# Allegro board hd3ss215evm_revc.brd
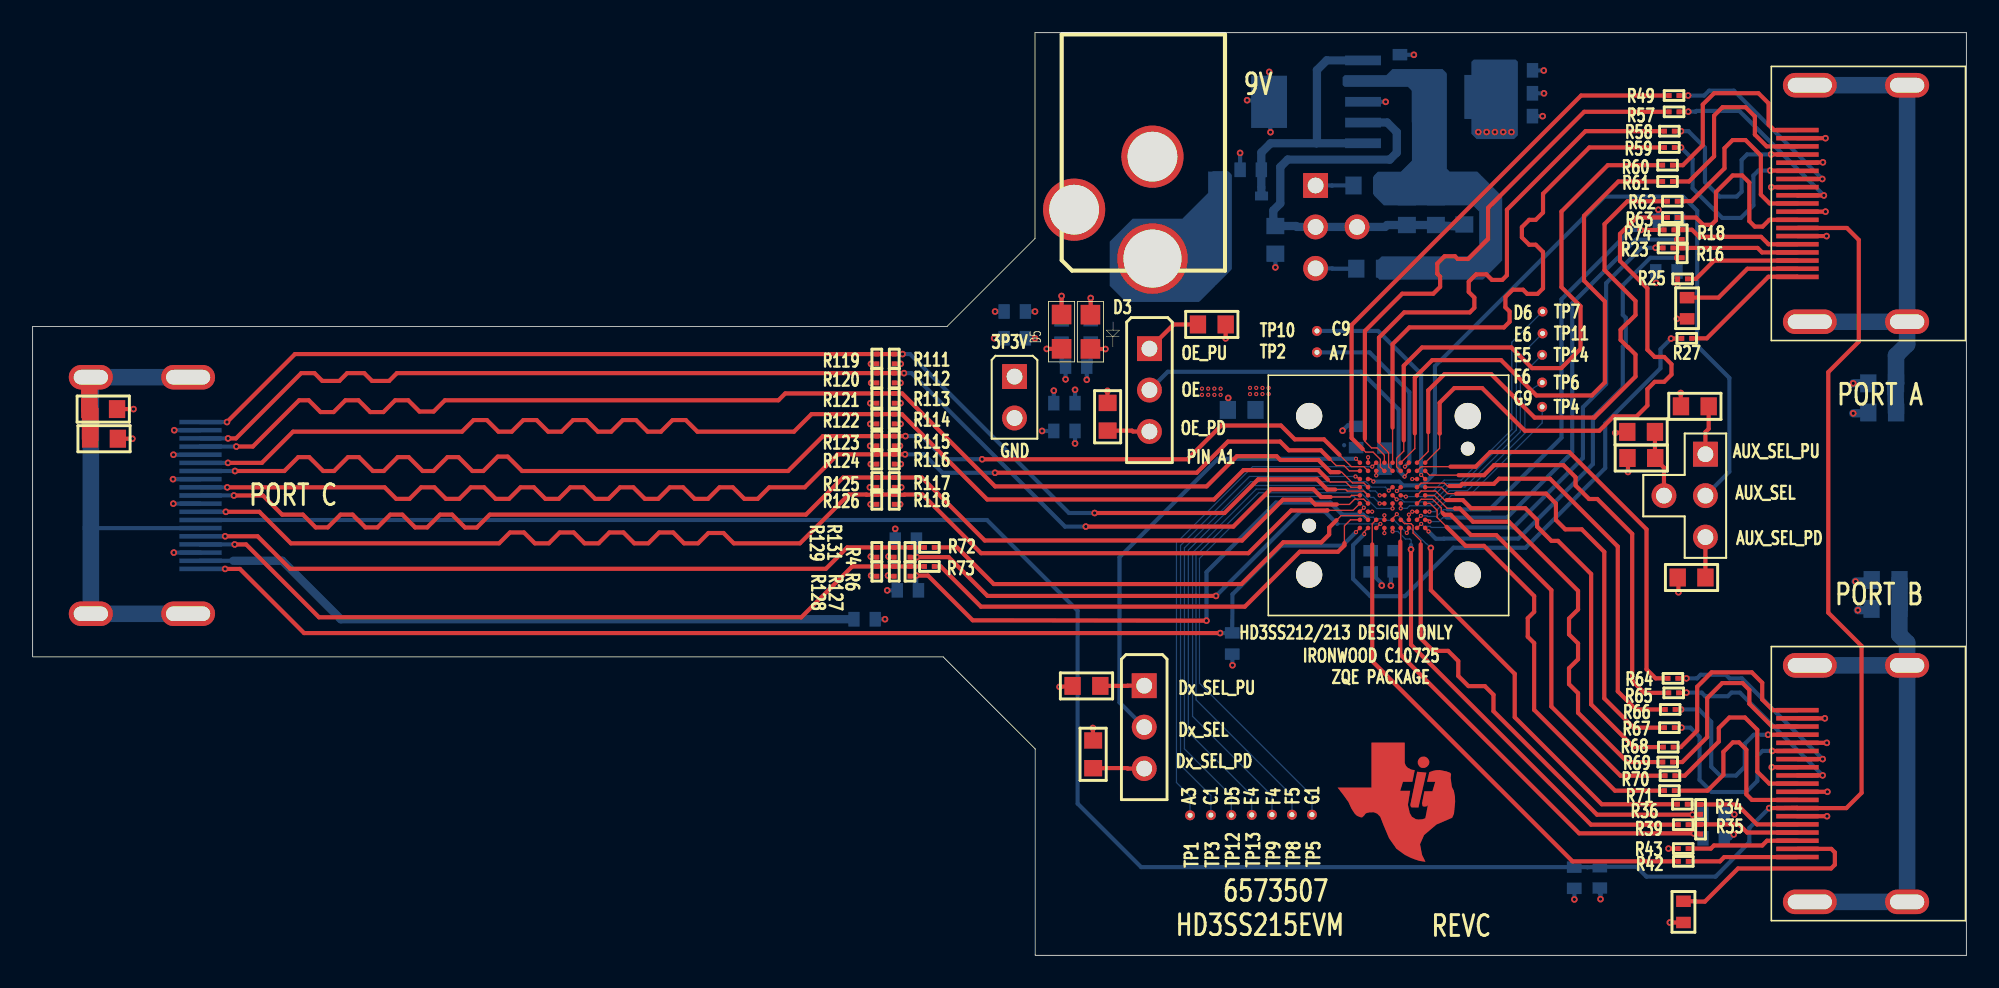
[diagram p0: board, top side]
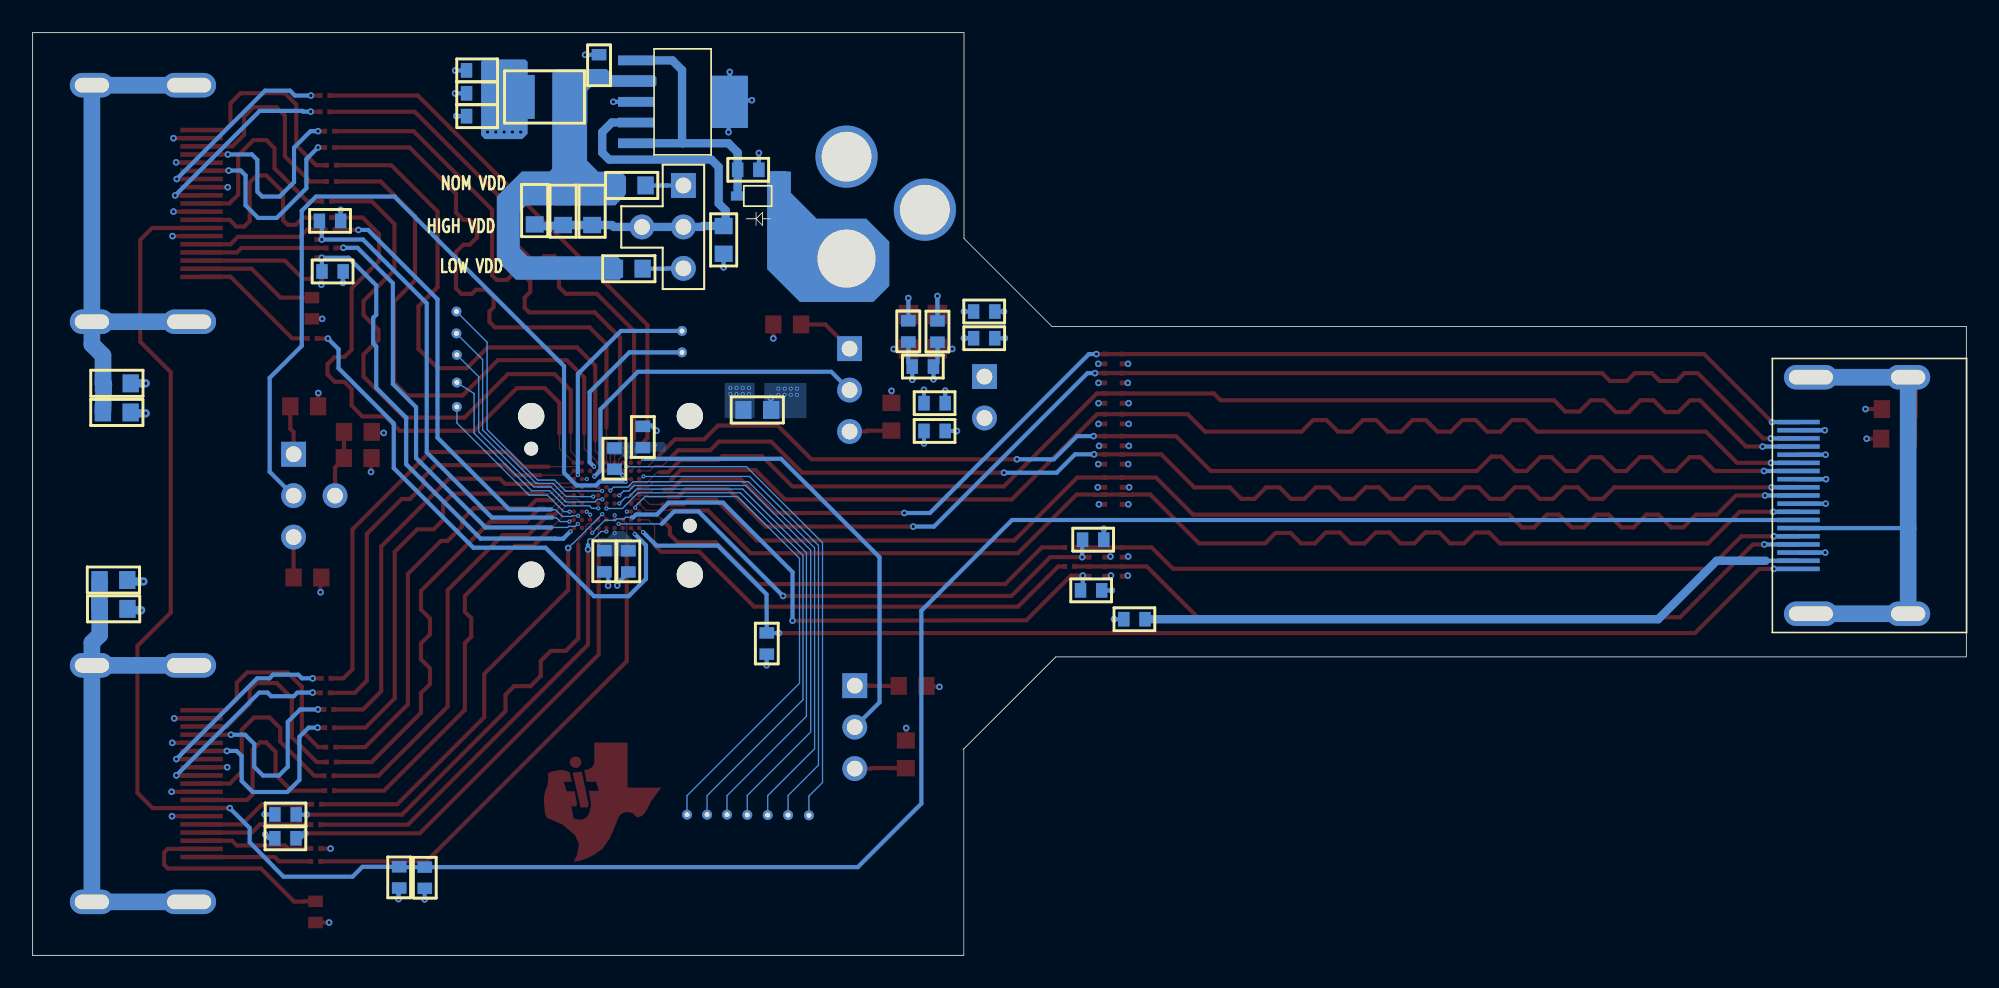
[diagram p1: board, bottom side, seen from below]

Outline 118.49 x 56.56 mm; copper layers: TOP, L2, L3, L4, L5, BOTTOM. Coordinates in mm from the lower left corner of the outline.
Outline path: 0,38.55 0,18.32 0.02,18.3 55.79,18.3 61.43,12.66 61.43,0.02 61.45,0 118.49,0 118.49,56.55 118.49,56.56 61.42,56.56 61.42,43.94 56.03,38.55 0,38.55

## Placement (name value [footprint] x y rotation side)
C20  1.0uF  [0603]  114.18 35.06 180 bottom
C37  1.0uF  [0603]  114.38 21.24 180 bottom
C65  0.1uF  [0402]  90.61 54.25 0 bottom
C66  0.01uF  [0402]  90.6 52.84 0 bottom
C67  1.0uF  [0402]  75.29 48.15 180 bottom
C68  0.1uF  [0402]  83.46 24.81 270 bottom
C69  0.1uF  [0402]  81.1 31.13 90 bottom
C70  0.01uF  [0402]  81.99 24.8 270 bottom
C71  0.01uF  [0402]  82.84 31.1 270 bottom
C73  1.0 uF  [0402]  90.6 51.44 0 bottom
C74  1.0 uF  [0402]  83.78 53.91 90 bottom
C75  1.0uF  [0603]  3.47 33.48 0 top
C76  0.1uF  [0402]  62.58 32.14 0 bottom
C77  0.1uF  [0402]  62.58 33.85 0 bottom
C78  0.01uF  [0402]  60.83 37.83 180 bottom
C79  0.01uF  [0402]  60.83 39.47 180 bottom
D3  GREEN  [LED_HSMB_C170DRA]  64.82 37.17 90 top
D4  10V, 3A  [SOD323]  74.06 46.55 180 bottom
D5  GREEN  [LED_HSMB_C170DRA]  63.05 37.18 90 top
J18  HDMI Female  [MOLEX_HDMI]  10.29 28.19 90 bottom
J21  HDMI Female  [MOLEX_HDMI]  108.14 46.09 90 top
J22  HDMI Female  [MOLEX_HDMI]  108.14 10.53 90 top
JMP4  4 Pin-T Berg Jumper  [BERG2X3TEE]  102.5 30.72 270 top
JMP9  DNI  [BERG2]  60.17 35.48 0 top
JMP10  DNI  [BERG2X3TEE]  78.62 47.19 270 bottom
JMP11  Header 3x1  [BERG1X3]  68.44 37.19 0 top
JMP13  Header 3x1  [BERG1X3]  68.12 16.53 0 top
L2  HI1206N101R-00  [1210]  85.73 52.62 0 bottom
NOREF  -  []  83.65 10.08 0 top
P1  RAPC722  [CON_RAPC722_JACK_THVT_3]  68.62 45.83 180 top
R2  DNI 100k  [0402]  73.51 18.46 90 bottom
R4  0  [0201]  53.76 25.01 270 top
R5  0  [0402]  51.63 20.6 180 bottom
R6  0  [0201]  53.76 23.84 270 top
R7  2K  [0402]  52.86 25.48 0 bottom
R8  2K  [0402]  52.98 22.37 0 bottom
R9  DNI 27K  [0402]  94.47 4.11 90 bottom
R10  DNI 5M  [0402]  96.03 5.43 270 bottom
R11  1M  [0603]  114.19 33.28 180 bottom
R14  100K  [0402]  100.76 41.92 180 bottom
R16  DNI 0  [0201]  101.08 42.76 90 top
R17  100K  [0402]  99.62 45.02 0 bottom
R18  DNI 0  [0201]  101.08 43.88 90 top
R20  0  [0402]  101.38 40.32 270 top
R22  4.64K  [0603]  73.11 38.67 180 top
R23  0  [0201]  99.91 43.36 0 top
R24  4.64K  [0603]  65.87 32.16 90 top
R25  0  [0201]  100.8 41.47 0 top
R27  0  [0201]  101.06 37.82 0 top
R28  4.64K  [0603]  101.01 33.66 0 top
R29  4.64K  [0603]  63.73 16.52 0 top
R30  4.64K  [0603]  102.5 23.16 180 top
R31  4.64K  [0603]  64.99 11.47 90 top
R33  100K  [0402]  103.65 8.64 180 bottom
R34  DNI 0  [0201]  102.21 8.65 90 top
R35  DNI 0  [0201]  102.21 7.43 90 top
R36  0  [0201]  100.79 9.26 0 top
R39  0  [0201]  100.84 8.01 0 top
R42  0  [0201]  100.85 5.76 0 top
R43  0  [0201]  100.84 6.55 0 top
R44  0  [0402]  101.16 3.31 270 top
R45  100K  [0402]  102.35 7.18 0 bottom
R46  1M  [0603]  114.39 23.01 180 bottom
R47  4.64K  [0603]  99.43 30.49 180 top
R48  4.64K  [0603]  97.71 32.09 0 top
R49  0  [0201]  100.28 52.7 0 top
R50  75  [0402]  64.84 37.6 90 bottom
R51  23.2K  [0603]  84.21 46.47 270 bottom
R52  150K  [0603]  85.99 46.47 270 bottom
R53  150K  [0603]  82.64 47.19 180 bottom
R54  DNI  [0603]  87.73 46.5 270 bottom
R55  64.9K  [0603]  82.81 42.09 180 bottom
R56  13K  [0603]  76.15 44.71 270 bottom
R57  0  [0201]  100.28 51.71 0 top
R58  0  [0201]  100 50.52 0 top
R59  0  [0201]  100 49.52 0 top
R60  0  [0201]  99.88 48.44 0 top
R61  0  [0201]  99.88 47.44 0 top
R62  0  [0201]  100.18 46.23 0 top
R63  0  [0201]  100.18 45.22 0 top
R64  0  [0201]  100.21 16.98 0 top
R65  0  [0201]  100.26 16.09 0 top
R66  0  [0201]  100.05 15.07 0 top
R67  0  [0201]  100 13.96 0 top
R68  0  [0201]  99.93 12.76 0 top
R69  0  [0201]  99.89 11.85 0 top
R70  0  [0201]  100.03 11.01 0 top
R71  0  [0201]  100 10.1 0 top
R72  DNI 0  [0201]  54.65 25.01 0 top
R73  DNI 0  [0201]  54.65 23.84 0 top
R74  0  [0201]  99.97 44.47 0 top
R75  0  [0603]  73.24 33.43 0 bottom
R111  DNI 10K  [0201]  52.8 36.26 90 top
R112  DNI 10K  [0201]  52.8 35.09 90 top
R113  DNI 10K  [0201]  52.8 33.85 90 top
R114  DNI 10K  [0201]  52.8 32.58 90 top
R115  DNI 10K  [0201]  52.8 31.23 90 top
R116  DNI 10K  [0201]  52.8 30.11 90 top
R117  DNI 10K  [0201]  52.8 28.69 90 top
R118  DNI 10K  [0201]  52.8 27.65 90 top
R119  DNI 10K  [0201]  51.73 36.26 90 top
R120  DNI 10K  [0201]  51.73 35.09 90 top
R121  DNI 10K  [0201]  51.73 33.85 90 top
R122  DNI 10K  [0201]  51.73 32.58 90 top
R123  DNI 10K  [0201]  51.73 31.23 90 top
R124  DNI 10K  [0201]  51.73 30.11 90 top
R125  DNI 10K  [0201]  51.73 28.69 90 top
R126  DNI 10K  [0201]  51.73 27.65 90 top
R127  DNI 1M  [0201]  52.8 23.84 270 top
R128  DNI 1M  [0201]  51.73 23.84 270 top
R129  DNI 10K  [0201]  51.73 25.01 270 top
R131  DNI 10K  [0201]  52.8 25.01 270 top
R132  100  [0402]  63.05 37.59 90 bottom
R133  DNI 0  [0402]  64.59 36.09 180 bottom
R134  1M  [0603]  3.52 31.67 0 top
TP1  Test Point  [TESTPOINTDRA]  70.92 8.59 0 top
TP2  Test Point  [TESTPOINTDRA]  78.7 36.96 0 top
TP3  Test Point  [TESTPOINTDRA]  72.2 8.6 0 top
TP4  Test Point  [TESTPOINTDRA]  92.5 33.62 0 top
TP5  Test Point  [TESTPOINTDRA]  78.39 8.62 0 top
TP6  Test Point  [TESTPOINTDRA]  92.5 35.11 0 top
TP7  Test Point  [TESTPOINTDRA]  92.52 39.46 0 top
TP8  Test Point  [TESTPOINTDRA]  77.17 8.62 0 top
TP9  Test Point  [TESTPOINTDRA]  75.94 8.62 0 top
TP10  Test Point  [TESTPOINTDRA]  78.7 38.28 0 top
TP11  Test Point  [TESTPOINTDRA]  92.52 38.12 0 top
TP12  Test Point  [TESTPOINTDRA]  73.45 8.6 0 top
TP13  Test Point  [TESTPOINTDRA]  74.7 8.61 0 top
TP14  Test Point  [TESTPOINTDRA]  92.5 36.81 0 top
U4  REG104-A  [DCQ_R-PDSO-G6]  78.67 52.32 180 bottom
U5  HD3SS215_ZQE  [IRONWOOD_81PIN_7048]  78.22 33.06 180 top

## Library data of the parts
C20 C37 C75 = cc0603
C65-C71 C73 C74 C76-C79 = cc0402
D3 D5 = LED_0603
D4 = BAT60A
J18 = HDMI A plug connector
J21 J22 = HDMI A plug connector1
JMP4 JMP10 = 4 Pin-T Berg Jumper
JMP9 = 2 Pin Berg Jumper
JMP11 JMP13 = Header 3x1
L2 = Ferrite Bead_1210_HI1206N10R-00
P1 = RAPC722
R2 R4-R10 R14 R16-R18 R20 R23 R25 R27 R33-R36 R39 R42-R45 R49-R75 R132 = r0402
R11 R22 R24 R28-R31 R46-R48 R134 = r0603
R111-R129 R131 = r0201
R133 = R
TP1-TP14 = Test Point
U4 = REG104
U5 = HD3SS213 ZQE_1

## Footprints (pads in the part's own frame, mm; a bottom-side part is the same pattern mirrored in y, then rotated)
0201
  rect 0.3x0.3 smd: 1(0,0) 2(0.599,0)
0402
  rect 0.701x0.899 smd: 1(0,0) 2(1.3,0)
0603
  rect 1.001x1.1 smd: 1(0,0) 2(1.699,0)
1210
  rect 1.6x2.7 smd: 1(0,0) 2(2.799,0)
BERG1X3
  rect 1.524x1.524 hole 0.965: 1(0,0)
  round 1.524 hole 0.965: 2(0,-2.54) 3(0,-5.08)
BERG2
  rect 1.524x1.524 hole 0.965: 1(0,0)
  round 1.524 hole 0.965: 2(0,-2.54)
BERG2X3TEE
  rect 1.524x1.524 hole 0.965: 1(0,0)
  round 1.524 hole 0.965: 2(2.54,0) 3(5.08,0) 4(2.54,-2.54)
CON_RAPC722_JACK_THVT_3
  round 3.81 hole 3.048: 1(0,-3.124) 2(4.801,0.127)
  round 4.318 hole 3.556: 3(0,3.124)
DCQ_R-PDSO-G6
  rect 2.2x0.599 smd: 1(-2.857,2.54) 2(-2.857,1.27) 3(-2.857,0) 4(-2.857,-1.27) 5(-2.857,-2.54)
  rect 2.2x3.2 smd: 6(2.901,0)
IRONWOOD_81PIN_7048
  round 1.61 hole 1.61 unplated: (-9.721,9.721) (-9.721,0) (0,9.721) (0,0)
  round 0.851 hole 0.851 unplated: (-9.721,1.999) (0,6.721)
  round 0.279 smd: A1(-3.109,2.86) A2(-3.609,2.86) A3(-4.11,2.86) A4(-4.61,2.86) A5(-5.11,2.86) A6(-5.611,2.86) A7(-6.111,2.86) A8(-6.609,2.86) A9(-7.109,2.86) B1(-3.109,3.36) B2(-3.609,3.36) B3(-4.11,3.36) B4(-4.61,3.36) B5(-5.11,3.36) B6(-5.611,3.36) B7(-6.111,3.36) B8(-6.609,3.36) B9(-7.109,3.36) C1(-3.109,3.861) C2(-3.609,3.861) C8(-6.609,3.861) C9(-7.109,3.861) D1(-3.109,4.361) D2(-3.609,4.361) D5(-5.11,4.361) D6(-5.611,4.361) D8(-6.609,4.361) D9(-7.109,4.361) E1(-3.109,4.859) E2(-3.609,4.859) E4(-4.61,4.859) E5(-5.11,4.859) E6(-5.611,4.859) E8(-6.609,4.859) E9(-7.109,4.859) F1(-3.109,5.359) F2(-3.609,5.359) F4(-4.61,5.359) F5(-5.11,5.359) F6(-5.611,5.359) F8(-6.609,5.359) F9(-7.109,5.359) G1(-3.109,5.86) G2(-3.609,5.86) G8(-6.609,5.86) G9(-7.109,5.86) H1(-3.109,6.36) H2(-3.609,6.36) H3(-4.11,6.36) H4(-4.61,6.36) H5(-5.11,6.36) H6(-5.611,6.36) H7(-6.111,6.36) H8(-6.609,6.36) H9(-7.109,6.36) J1(-3.109,6.861) J2(-3.609,6.861) J3(-4.11,6.861) J4(-4.61,6.861) J5(-5.11,6.861) J6(-5.611,6.861) J7(-6.111,6.861) J8(-6.609,6.861) J9(-7.109,6.861)
LED_HSMB_C170DRA
  rect 1.199x1.199 smd: 1(0,0) 2(2.101,0)
MOLEX_HDMI
  rect 0.279x2.601 smd: 1(4.501,0) 2(4,0) 3(3.5,0) 4(3,0) 5(2.499,0) 6(1.999,0) 7(1.501,0) 8(1.001,0) 9(0.5,0) 10(0,0) 11(-0.5,0) 12(-1.001,0) 13(-1.501,0) 14(-1.999,0) 15(-2.499,0) 16(-3,0) 17(-3.5,0) 18(-4,0) 19(-4.501,0)
  oval 1.501x3.299 hole 0.899x2.7: 20(-7.249,-0.759) 21(7.249,-0.759)
  oval 1.501x2.7 hole 0.899x2.101: 22(-7.249,-6.721) 23(7.249,-6.721)
SOD323
  rect 0.8x0.551 smd: 1(-1.24,0) 2(1.24,0)
TESTPOINTDRA
  round 0.61 hole 0.305: 1(0,0)

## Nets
9V_DC_IN: C67.1 D4.1(C) U4.1(VIN) U4.5(ENABLE)
9V_WALL_IN: D4.2(A) P1.3(TIP)
GND: C20.2 C37.2 C65.2 C66.2 C67.2 C68.2 C69.2 C70.2 C71.2 C73.2 C74.2 C75.2 C76.2 C77.2 C78.2 C79.2 D3.1 D5.1 J18.2(GND1) J18.5(GND2) J18.8(GND3) J18.11(GND4) J18.17(DDC GND) J21.2(GND1) J21.5(GND2) J21.8(GND3) J21.11(GND4) J21.14(UTILITY) J22.2(GND1) J22.5(GND2) J22.8(GND3) J22.11(GND4) J22.14(UTILITY) JMP9.2 P1.1(SLEEVE) R2.1 R10.2 R11.2 R17.1 R24.2 R25.1 R30.2 R31.2 R33.1 R43.1 R46.2 R47.2 R56.2 R119.1 R120.1 R121.1 R122.1 R123.1 R124.1 R125.1 R126.1 R128.2 R129.2 R134.2 U4.3(GND1) U4.6(GND2) U5.B3(GND#B3) U5.C8(GND#C8) U5.G2(GND#G2) U5.G8(GND#G8) U5.H4(GND#H4) U5.H7(GND#H7)
SGND2: C20.1 J21.20(CH_GND1) J21.21(CH_GND2) J21.22(CH_GND3) J21.23(CH_GND4) R11.1
SGND3: C37.1 J22.20(CH_GND1) J22.21(CH_GND2) J22.22(CH_GND3) J22.23(CH_GND4) R46.1
3P3V: C65.1 C66.1 C73.1 JMP9.1 L2.2 R14.2 R22.1 R28.1 R29.1 R45.2 R48.1 R50.1 R75.1 R111.1 R112.1 R113.1 R114.1 R115.1 R116.1 R117.1 R118.1 R127.2 R131.2 R133.1
3P3V_R: C68.1 C69.1 C70.1 C71.1 R75.2 U5.A2(VCC#A2) U5.J4(VCC#J4)
3P3V_REG: C74.1 L2.1 R51.1 R52.1 R53.1 R54.1 R55.1 U4.2(VOUT)
5V/3P3V: C76.1 C77.1 C78.1 C79.1 R5.1 R7.1 R8.1 R9.1 R20.2 R44.2 R132.1 R133.2
AUX SEL: JMP4.2 U5.C2(AUX_SEL)
AUX SEL MID: JMP4.4 R47.1 R48.2
AUX SEL PULL DOWN: JMP4.3 R30.1
AUX SEL PULL UP: JMP4.1 R28.2
AUX_SINK_OUTPUT_N: R14.1 R16.1 U5.J9(DA_AUX_N)
AUX_SINK_OUTPUT_N_DDC_SDA: J21.16(SDA) R16.2 R23.2
AUX_SINK_OUTPUT_P: R17.2 R18.1 U5.H9(DA_AUX_P)
AUX_SINK_OUTPUT_P_DDC_SCL: J21.15(SCL) R18.2 R74.2
CEC: J18.13(CEC) J21.13(CEC) J22.13(CEC) R9.2 R10.1
DA_0N: R57.1 U5.A4(DA_0_N)
DA_0P: R49.1 U5.B4(DA_0_P)
DA_1N: R59.1 U5.A5(DA_1_N)
DA_1P: R58.1 U5.B5(DA_1_P)
DA_2N: R61.1 U5.A6(DA_2_N)
DA_2P: R60.1 U5.B6(DA_2_P)
DA_CLKN: R63.1 U5.A9(DA_3_N)
DA_CLKP: R62.1 U5.A8(DA_3_P)
DA_HPD: R27.1 U5.J2(DA_HPD)
DA_HPD_R: J21.19(HPD) R27.2
DB_0N: R65.1 U5.B9(DB_0_N)
DB_0P: R64.1 U5.B8(DB_0_P)
DB_1N: R67.1 U5.D9(DB_1_N)
DB_1P: R66.1 U5.D8(DB_1_P)
DB_2N: R69.1 U5.E9(DB_2_N)
DB_2P: R68.1 U5.E8(DB_2_P)
DB_AUX_SINK_OUTPUT_N: R35.1 R45.1 U5.J6(DB_AUX_N)
DB_AUX_SINK_OUTPUT_N_OR_SDA: J22.16(SDA) R35.2 R39.2
DB_AUX_SINK_OUTPUT_P: R33.2 R34.1 U5.H6(DB_AUX_P)
DB_AUX_SINK_OUTPUT_P_OR_DDC_SCL: J22.15(SCL) R34.2 R36.2
DB_CLKN: R71.1 U5.F9(DB_3_N)
DB_CLKP: R70.1 U5.F8(DB_3_P)
DB_DDC_SCL: R36.1 U5.H5(DB_DDCCLK)
DB_DDC_SDA: R39.1 U5.J5(DB_DDCDBT)
DB_HPD: R42.1 U5.H3(DB_HPD)
DB_HPD_R: J22.19(HPD) R42.2
DDC_SCL: R74.1 U5.H8(DA_DDCCLK)
DDC_SDA: R23.1 U5.J8(DA_DDCDAT)
DX SEL PULL DOWN: JMP13.3 R31.1
DX SEL PULL UP: JMP13.1 R29.2
DX_SEL: JMP13.2 U5.A1(DX_SEL)
HIGH VDD: JMP10.2 JMP10.4 R51.2 R52.2 R54.2 R56.1 U4.4(NR/ADJUST)
LOW VDD: JMP10.3 R55.2
NOM VDD: JMP10.1 R53.2
OE PULL DOWN: JMP11.3 R24.1
OE PULL UP: JMP11.1 R22.2
OUTPUT ENABLE: JMP11.2 U5.B7(OE)
SOURCE_CLK_N: J18.12(CLKN) R118.2 R126.2 U5.F1(DC_3_N)
SOURCE_CLK_P: J18.10(CLKP) R117.2 R125.2 U5.F2(DC_3_P)
SOURCE_DDC_CLK: R4.2 R7.2 U5.J3(DC_DDC_CLK)
SOURCE_DDC_SDA: R6.2 R8.2 U5.J7(DC_DDC_SDA)
SOURCE_DP_AUX_N_C: R73.2 U5.H1(DC_AUX_N)
SOURCE_DP_AUX_P_C: R72.2 U5.H2(DC_AUX_P)
SOURCE_HPD_C: J18.19(HPD) R2.2 U5.J1(DC_HPD)
SOURCE_TMDS_CLK_P: J18.15(SCL) R4.1 R72.1 R129.1 R131.1
SOURCE_TMDS_ML_0N: J18.3(D2N) R112.2 R120.2 U5.E1(DC_0_N)
SOURCE_TMDS_ML_0P: J18.1(D2P) R111.2 R119.2 U5.E2(DC_0_P)
SOURCE_TMDS_ML_1N: J18.6(D1N) R114.2 R122.2 U5.D1(DC_1_N)
SOURCE_TMDS_ML_1P: J18.4(D1P) R113.2 R121.2 U5.D2(DC_1_P)
SOURCE_TMDS_ML_2N: J18.9(D0N) R116.2 R124.2 U5.B1(DC_2_N)
SOURCE_TMDS_ML_2P: J18.7(D0P) R115.2 R123.2 U5.B2(DC_2_P)
SOURCE_TMDS_SDA_N: J18.16(SDA) R6.1 R73.1 R127.1 R128.1
N16816313: D3.2 R50.2
N16845167: J18.18(5V) R5.2
N17461751: J21.7(D0P) R49.2
N17461760: J21.9(D0N) R57.2
N17461769: J21.4(D1P) R58.2
N17461772: J21.6(D1N) R59.2
N17461775: J21.1(D2P) R60.2
N17461784: J21.3(D2N) R61.2
N17461793: J21.10(CLKP) R62.2
N17461802: J21.12(CLKN) R63.2
N17518625: J21.18(5V) R20.1
N17521117: J22.7(D0P) R64.2
N17521123: J22.9(D0N) R65.2
N17521129: J22.4(D1P) R66.2
N17521131: J22.6(D1N) R67.2
N17521133: J22.1(D2P) R68.2
N17521137: J22.3(D2N) R69.2
N17521143: J22.10(CLKP) R70.2
N17521149: J22.12(CLKN) R71.2
N17522573: J22.17(DDC GND) R43.2
N17522869: J22.18(5V) R44.1
N17527182: TP1.1 U5.A3(NC1)
N17527888: TP2.1 U5.A7(NC2)
N17528001: TP3.1 U5.C1(NC3)
N17528028: TP4.1 U5.G9(NC14)
N17528033: TP5.1 U5.G1(NC13)
N17528049: TP6.1 U5.F6(NC12)
N17528125: TP8.1 U5.F5(NC11)
N17528132: TP7.1 U5.D6(NC4)
N17528155: TP10.1 U5.C9(NC5)
N17528163: TP9.1 U5.F4(NC10)
N17528201: TP12.1 U5.D5(NC6)
N17528206: TP11.1 U5.E6(NC9)
N17528242: TP13.1 U5.E4(NC7)
N17528247: TP14.1 U5.E5(NC8)
N17577047: D5.2 R132.2
N17584630: J21.17(DDC GND) R25.2
N17593880: C75.1 J18.14(UTILITY) J18.20(CH_GND1) J18.21(CH_GND2) J18.22(CH_GND3) J18.23(CH_GND4) R134.1

Pads without a net: P1 2

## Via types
v1: diameter 0.406, hole 0.203, TOP to BOTTOM, 146 vias
v2: diameter 0.254, hole 0.127, TOP to BOTTOM, 51 vias

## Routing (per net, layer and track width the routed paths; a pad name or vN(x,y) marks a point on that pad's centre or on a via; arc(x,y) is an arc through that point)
9V_DC_IN: length 16.7
  BOTTOM w0.508: D4.1 75.29,47.09 C67.1 75.29,49.21 75.86,49.78 78.66,49.78 ; 78.66,49.78 U4.5 ; 78.66,49.78 78.7,49.82 78.7,54.26 79.29,54.86 U4.1
GND: length 88.7
  TOP w0.076: U5.G8 v2(84.54,27.2) ; U5.H4 v2(82.83,26.97) ; U5.C8 v2(84.54,29.2) ; U5.H7 v2(84.33,27.02) ; U5.G2 v2(82.08,27.2) ; U5.B3 v2(82.33,29.42)
  TOP w0.254: J21.2 v1(109.86,50.09) ; J22.8 v1(106.57,11.53) ; v1(65.86,34.6) 65.86,33.87 R24.2 ; R121.1 v1(51.33,33.85) ; R128.2 51.42,23.24 v1(51.38,23.28) ; R125.1 v1(51.3,28.69) ; v1(64.97,13.94) R31.2 ; R43.1 v1(100.24,6.55) ; R126.1 v1(51.35,27.65) ; J21.5 v1(109.7,48.61) ; J22.14 v1(109.95,8.53) ; J22.5 v1(109.94,13.03) ; v1(51.36,24.45) 51.4,24.41 R129.2 ; J22.11 v1(109.98,10.03) ; v1(97.76,29.63) 97.76,30.45 R47.2 ; R119.1 v1(51.37,36.26) ; J22.2 v1(109.82,14.53) ; R123.1 v1(51.32,31.23) ; D3.1 v1(65.74,37.17) ; J21.11 v1(109.86,45.59) ; J21.14 v1(109.93,44.09) ; J21.8 v1(106.54,47.09) ; D5.1 v1(62.14,37.17) ; R120.1 v1(51.38,35.09) ; C75.2 v1(6.18,33.48) ; R124.1 v1(51.36,30.11) ; v1(100.85,22.26) 100.85,23.12 R30.2 ; R134.2 v1(6.11,31.67) ; R122.1 v1(51.33,32.58) ; R25.1 v1(100.8,41.11)
  L2 w0.254: JMP9.2 61.05,32.94 ; JMP9.2 59.29,32.94 ; JMP9.2 60.17,32.06 ; JMP9.2 60.17,33.82
  L2 w0.762: 68.62,46.62 P1.1 ; P1.1 66.28,48.96 ; P1.1 68.62,51.3 ; P1.1 70.96,48.96
  L5 w0.254: 60.17,32.06 JMP9.2 ; JMP9.2 61.05,32.94 ; JMP9.2 59.29,32.94 ; JMP9.2 60.17,33.82
  L5 w0.762: 68.62,46.62 P1.1 ; P1.1 66.28,48.96 ; P1.1 68.62,51.3 ; P1.1 70.96,48.96
  BOTTOM w0.254: v1(82.67,22.67) 82.67,22.78 82.07,23.39 C70.2 ; C78.2 v1(58.92,37.83) ; R17.1 99.62,45.08 99.62,45.11 v1(99.62,45.7) ; R10.2 96.03,3.81 96.08,3.77 v1(96.08,3.45) ; U4.6 v1(75.85,50.46) ; U4.6 v1(75.78,54.15) ; U4.6 v1(74.42,52.42) ; C77.2 v1(63.88,34.67) ; J18.17 v1(8.65,24.69) ; v1(83.23,22.66) 83.23,23.2 83.46,23.44 C68.2 ; R2.1 v1(73.52,17.78) ; C71.2 82.7,29.8 v2(82.33,29.42) ; C67.2 v1(73.99,49.18) ; U4.3 v1(82.91,52.32) ; v1(80.27,32.16) 80.59,32.49 81.04,32.49 C69.2 ; C73.2 v1(92.53,51.44) ; R56.2 v1(76.15,42.17) ; R33.1 v1(104.27,8.64) ; C76.2 v1(63.88,31.38) ; C79.2 v1(58.98,39.47) ; C74.2 v1(84.64,55.2) ; C66.2 v1(92.61,52.84) ; J18.2 v1(8.68,32.19) ; J18.5 v1(8.63,30.69) ; J18.11 v1(8.62,27.69) ; C65.2 v1(92.6,54.24) ; J18.8 v1(8.6,29.19)
  BOTTOM w0.508: v1(111.56,35.06) C20.2 ; v1(111.56,33.23) 112.44,33.23 R11.2 ; R46.2 112.61,22.92 v1(111.7,22.92) ; C37.2 112.6,21.16 v1(111.85,21.16)
SGND2: length 32.3
  BOTTOM w1.016: J21.22 114.86,37.45 114.18,36.77 C20.1 114.13,35.01 R11.1 ; J21.22 J21.20 ; J21.22 J21.23 J21.21
SGND3: length 31.9
  BOTTOM w1.016: J22.20 J22.22 J22.23 ; J22.21 J22.23 ; J22.23 114.86,19.16 114.38,19.64 C37.1 114.41,21.27 R46.1
3P3V: length 15.7
  TOP w0.254: R114.1 v1(53.19,32.58) ; R111.1 v1(53.19,36.26) ; R29.1 v1(62.93,16.46) ; R116.1 v1(53.2,30.11) ; R22.1 v1(73.11,37.82) ; R131.2 52.49,24.41 v1(52.45,24.45) ; R127.2 52.46,23.24 v1(52.42,23.28) ; R112.1 v1(53.18,35.09) ; R118.1 v1(53.15,27.65) ; R117.1 v1(53.23,28.69) ; R28.1 v1(100.99,34.47) ; R48.1 v1(96.98,32.02) ; R115.1 v1(53.15,31.23) ; R113.1 v1(53.18,33.85)
  L3 w0.254: JMP9.1 60.17,36.51 ; JMP9.1 61.2,35.48 ; JMP9.1 60.17,34.45 ; JMP9.1 59.14,35.48
  BOTTOM w0.254: R14.2 99.48,41.9 v1(99.48,41.22) ; R45.2 104,7.18 v1(104.24,7.41) ; R50.1 64.84,36.33 R133.1 v1(64.59,35.28) ; R75.1 v1(73.26,34.17)
  vias: v1(88.59,50.47) v1(89.1,50.47) v1(89.6,50.47) v1(90.11,50.47) v1(90.62,50.47) v2(71.65,34.74) v2(71.65,34.36) v2(72.03,34.74) v2(72.03,34.36) v2(72.42,34.74) v2(72.42,34.36) v2(72.8,34.74) v2(72.8,34.36)
3P3V_R: length 0.7
  TOP w0.076: U5.J4 v2(82.83,25.88) ; U5.A2 v2(81.83,30.54)
  BOTTOM w0.254: 80.37,31.27 80.37,31.28
  vias: v2(74.6,34.79) v2(74.6,34.4) v2(74.98,34.79) v2(74.98,34.4) v2(75.36,34.79) v2(75.36,34.4) v2(75.74,34.79) v2(75.74,34.4)
5V/3P3V: length 9.1
  TOP w0.254: R20.2 v1(100.75,39.02) ; R44.2 v1(100.32,2.01)
  BOTTOM w0.254: R9.1 94.47,4.1 v1(94.47,3.43) ; C77.1 v1(62.58,34.62) ; R8.1 v1(52.37,22.37) ; C79.1 v1(61.42,39.47) ; v1(63.29,35.31) R133.2 63.05,36.34 R132.1 ; C76.1 v1(61.86,32.14) ; R5.1 v1(52.23,20.6) ; R7.1 v1(52.86,26.15) ; C78.1 v1(61.42,37.83)
AUX SEL: length 50.7
  TOP w0.076: v2(82.16,29.04) 82.01,29.2 U5.C2
  BOTTOM w0.254: v2(82.16,29.04) 83.74,29.04 83.98,28.8 85.15,28.8 85.93,29.58 85.93,36.12 96.32,46.51 101.13,46.51 102,45.64 102,37.36 103.97,35.39 103.97,29.64 JMP4.2
AUX SEL MID: length 4.1
  TOP w0.254: JMP4.4 99.96,29.9 99.43,30.43 R47.1 99.41,30.5 R48.2
AUX SEL PULL DOWN: length 2.5
  TOP w0.254: JMP4.3 R30.1
AUX SEL PULL UP: length 3
  TOP w0.254: R28.2 102.7,32.28 102.5,32.08 JMP4.1
AUX_SINK_OUTPUT_N: length 29.5
  TOP w0.076: U5.J9 85.33,26.19 v2(85.54,25.98)
  TOP w0.254: R16.1 v1(100.78,42.76)
  BOTTOM w0.254: v2(85.54,25.98) 85.98,25.54 86.48,25.54 86.48,25.54 91.04,25.54 95.61,30.11 95.61,32.96 97.44,34.79 97.44,37.33 97.62,37.51 97.62,39.08 97.44,39.27 97.44,41.07 99.13,42.76 v1(100.78,42.76) R14.1
AUX_SINK_OUTPUT_N_DDC_SDA: length 7.7
  TOP w0.254: J21.16 105.98,43.09 105.7,43.36 101.49,43.36 101.49,43.36 R16.2 R23.2
AUX_SINK_OUTPUT_P: length 29.5
  TOP w0.076: v2(85.6,26.59) 85.49,26.7 U5.H9
  TOP w0.254: R18.1 v1(100.78,43.88)
  BOTTOM w0.076: 86.66,26.83 86.64,26.82 86.4,26.82 86.17,26.59 v2(85.6,26.59)
  BOTTOM w0.254: R17.2 100.78,44.88 v1(100.78,43.88) 98.25,43.88 94.34,39.97 94.34,30.83 90.34,26.83 86.66,26.83
AUX_SINK_OUTPUT_P_DDC_SCL: length 7.9
  TOP w0.254: J21.15 106.37,43.59 105.92,44.04 102.11,44.04 101.68,44.48 R18.2 100.58,44.48 R74.2
CEC: length 160
  TOP w0.254: v1(106.41,9.03) 108.13,9.04 J22.13 111.14,9.03 112.07,9.96 112.07,18.97 110.03,21.01 110.03,35.75 111.9,37.62 111.9,43.86 111.17,44.59 J21.13
  BOTTOM w0.254: v1(106.41,9.03) 105.19,7.81 105.19,6.94 103.12,4.82 98.89,4.82 98.28,5.43 R10.1 95.27,5.4 95.26,5.41 R9.2 67.93,5.41 64.04,9.3 64.04,21.13 58.48,26.69 J18.13
DA_0N: length 35.3
  TOP w0.076: 81.64,31.66 81.64,31.51 82.04,31.11 82.38,31.11 82.83,30.66 U5.A4
  TOP w0.254: R57.1 95.07,51.71 89.18,45.82 89.18,43.91 87.96,42.68 87.33,42.68 87.15,42.86 86.52,42.86 86.07,42.41 86.07,41.78 86.25,41.61 86.25,40.98 85.83,40.56 83.92,40.56 81.64,38.27 81.64,31.66
DA_0P: length 35.3
  TOP w0.076: 81.5,31.04 81.69,30.85 82.14,30.85 82.59,30.4 82.59,29.94 U5.B4
  TOP w0.254: 81.5,31.04 80.82,31.71 80.82,38.64 94.89,52.7 R49.1
DA_1N: length 35.3
  TOP w0.076: 83.33,32.35 U5.A5
  TOP w0.254: 83.33,32.35 83.33,37.46 84.36,38.49 90.16,38.49 90.51,38.84 90.51,39.47 90.25,39.72 90.25,40.35 90.7,40.8 91.33,40.8 91.58,40.55 92.21,40.55 92.55,40.88 92.55,43.11 92.11,43.56 91.7,43.56 91.26,44.01 91.26,44.64 91.7,45.09 92.11,45.09 92.55,45.53 92.55,46.68 95.39,49.52 R59.1
DA_1P: length 35.3
  TOP w0.076: 82.5,31.51 82.5,31.41 83.09,30.82 83.09,29.94 U5.B5
  TOP w0.254: 82.5,31.51 82.5,37.87 84.05,39.41 88.06,39.41 88.34,39.69 88.34,40.32 88,40.67 88,41.3 88.45,41.74 89.08,41.74 89.42,41.4 90.05,41.4 90.34,41.69 90.34,45.71 95.15,50.52 R58.1
DA_2N: length 35.3
  TOP w0.076: U5.A6 84.7,31.06 84.7,32
  TOP w0.254: R61.1 97.17,47.44 95.06,45.33 95.06,41.36 96.34,40.08 96.34,35.12 95.54,34.32 92.15,34.32 89.98,36.48 85.76,36.48 84.7,35.42 84.7,32
DA_2P: length 35.3
  TOP w0.076: U5.B6 83.58,29.95 83.58,30.47 84.02,30.91 84.02,31.57
  TOP w0.254: R60.1 96.52,48.44 93.68,45.6 93.68,40.96 94.85,39.79 94.85,37.18 93.67,35.99 91.88,35.99 90.61,37.26 85.14,37.26 84.02,36.14 84.02,31.57
DA_CLKN: length 35.3
  TOP w0.076: 86.21,31.99 86.21,31.08 U5.A9
  TOP w0.254: 86.21,31.99 86.22,32 86.22,33.87 87.12,34.77 88.82,34.77 91.44,32.16 96,32.16 96.88,33.04 98.28,33.04 98.95,33.7 98.95,34.71 99.4,35.16 99.98,35.16 100.42,35.6 100.42,36.23 99.98,36.68 99.4,36.68 98.95,37.13 98.95,40.89 97.27,42.57 97.27,44.22 98.27,45.22 R63.1
DA_CLKP: length 35.3
  TOP w0.076: U5.A8 85.52,30.89 85.52,32.07
  TOP w0.254: R62.1 97.72,46.23 96.32,44.83 96.32,42.01 98.22,40.11 98.22,39.25 97.77,38.8 97.75,38.8 97.31,38.35 97.31,37.72 97.75,37.28 97.77,37.28 98.22,36.83 98.22,35.48 95.7,32.96 92.04,32.96 89.37,35.63 86.51,35.63 85.52,34.63 85.52,32.07
DA_HPD: length 32.9
  TOP w0.076: U5.J2 81.59,25.96 v2(81.59,25.83)
  TOP w0.254: R27.1 101.05,37.81 v1(100.4,37.81)
  BOTTOM w0.254: v2(81.59,25.83) 80.91,25.14 80.91,23.08 81.97,22.02 84.09,22.02 87.06,24.99 91.49,24.99 96.37,29.87 96.37,32.61 99.75,35.99 99.75,37.16 v1(100.4,37.81)
DA_HPD_R: length 8.1
  TOP w0.254: J21.19 108.13,41.6 106.36,41.6 102.59,37.82 R27.2
DB_0N: length 26.6
  TOP w0.076: U5.B9 85.6,29.43 87.38,29.43
  TOP w0.254: R65.1 98.76,16.09 98.02,16.83 98.02,25.84 95.88,27.97 95.38,27.97 94.55,28.8 94.55,29.3 93.8,30.05 89.55,30.05 88.94,29.43 87.38,29.43
DB_0P: length 26.6
  TOP w0.076: 86.88,29.96 85.09,29.96 U5.B8
  TOP w0.254: R64.1 99.45,16.98 98.89,17.54 98.89,26.11 94.16,30.85 89.32,30.85 88.43,29.96 86.88,29.96
DB_1N: length 26.6
  TOP w0.076: 87.23,28.3 86.71,28.3 86.32,28.7 U5.D9
  TOP w0.254: R67.1 98.1,13.96 96.31,15.75 96.31,24.73 94.92,26.11 93.92,26.11 93.34,26.69 93.34,27.7 92.74,28.3 87.23,28.3
DB_1P: length 26.6
  TOP w0.076: 86.81,28.77 86.69,28.77 86.51,28.95 85.08,28.95 U5.D8
  TOP w0.254: 86.81,28.77 87.48,28.77 87.61,28.9 89.54,28.9 89.86,29.22 92.98,29.22 97.13,25.06 97.13,16.18 98.24,15.07 R66.1
DB_2N: length 26.6
  TOP w0.076: 87.16,27.4 86.68,27.4 85.89,28.2 U5.E9
  TOP w0.254: R69.1 97.72,11.85 94.7,14.87 94.7,16.07 94.15,16.63 94.15,17.6 94.7,18.15 94.7,19.12 94.15,19.67 94.15,20.65 94.7,21.2 94.7,22.34 90.46,26.58 88.26,26.58 87.45,27.39 87.17,27.39 87.16,27.4
DB_2P: length 26.6
  TOP w0.076: 86.65,27.91 86.53,27.91 85.98,28.46 85.09,28.46 U5.E8
  TOP w0.254: R68.1 98.12,12.76 95.5,15.38 95.5,23.38 93.47,25.41 93.07,25.41 92.19,26.29 92.19,26.69 91.47,27.41 88.14,27.41 87.64,27.91 86.65,27.91
DB_AUX_SINK_OUTPUT_N: length 31.4
  TOP w0.076: 83.81,25.36 83.83,25.39 U5.J6
  TOP w0.254: 83.81,25.36 83.81,18.44 94.77,7.48 v1(101.79,7.48) R35.1
  BOTTOM w0.254: R45.1 102.1,7.18 v1(101.79,7.48)
DB_AUX_SINK_OUTPUT_N_OR_SDA: length 6.9
  TOP w0.254: R39.2 101.45,8.01 102.01,8.01 102.03,8.03 R35.2 102.61,8.03 102.62,8.03 104.56,8.03 105.06,7.53 J22.16
DB_AUX_SINK_OUTPUT_P: length 31.4
  TOP w0.076: 85.06,25.19 85.06,25.42 84.59,25.89 84.59,26.34 84.47,26.46 84.07,26.46 U5.H6
  TOP w0.254: 85.06,25.19 85.06,19.43 85.82,18.66 86.74,18.66 87.36,18.04 87.36,17.13 87.98,16.5 88.99,16.5 89.52,15.97 89.52,14.97 95.86,8.63 v1(101.71,8.63) 102.18,8.63 R34.1
  BOTTOM w0.254: R33.2 102.33,8.63 v1(101.71,8.63)
DB_AUX_SINK_OUTPUT_P_OR_DDC_SCL: length 7.3
  TOP w0.254: R36.2 102.02,9.26 102.03,9.25 R34.2 104.44,9.25 105.66,8.03 J22.15
DB_CLKN: length 26.6
  TOP w0.076: 86.64,26.27 86.06,26.85 86.06,27.28 85.65,27.7 U5.F9
  TOP w0.254: R71.1 96.96,10.1 92.01,15.05 92.01,19.14 91.62,19.53 91.62,20.67 92.01,21.06 92.01,22.02 88.93,25.1 87.81,25.1 86.64,26.27
DB_CLKP: length 26.6
  TOP w0.076: 86.4,27.12 86.32,27.2 86.32,27.42 85.79,27.96 85.09,27.96 U5.F8
  TOP w0.254: 86.4,27.12 86.51,27.01 86.89,27.01 88.14,25.76 89.68,25.76 93.06,22.39 93.06,15.25 97.3,11.01 R70.1
DB_DDC_SCL: length 28.1
  TOP w0.076: U5.H5 83.33,26.78 v2(83.59,27.04)
  TOP w0.254: v1(85.68,24.97) 85.68,22.4 90.82,17.25 90.82,14.59 96.15,9.26 R36.1
  BOTTOM w0.076: v2(83.59,27.04) 85.39,25.24 85.42,25.24 v1(85.68,24.97)
DB_DDC_SDA: length 28.9
  TOP w0.076: U5.J5 v2(83.33,25.98)
  TOP w0.254: R39.1 95.49,8.01 84.46,19.04 v1(84.46,24.88)
  BOTTOM w0.076: 84.47,25.15 84.47,25.45 84.39,25.52 84.12,25.52 83.66,25.98 v2(83.33,25.98)
  BOTTOM w0.254: v1(84.46,24.88) 84.46,25.14 84.47,25.15
DB_HPD: length 32.6
  TOP w0.076: 82.09,25.19 82.09,26.45 U5.H3
  TOP w0.254: 82.09,25.19 82.09,18.03 94.36,5.76 R42.1
DB_HPD_R: length 6.8
  TOP w0.254: J22.19 103.66,6.03 103.4,5.76 R42.2
DDC_SCL: length 27.5
  TOP w0.076: v2(85.07,26.94) 85.07,26.94 U5.H8
  TOP w0.254: R74.1 v1(98.53,44.47)
  BOTTOM w0.076: v2(85.07,26.94) 85.43,26.94 85.47,26.91 86.03,26.91 86.45,27.32 86.69,27.32 86.71,27.34
  BOTTOM w0.254: v1(98.53,44.47) 97.93,44.47 93.69,40.22 93.69,31.73 89.29,27.34 86.71,27.34
DDC_SDA: length 27.8
  TOP w0.076: U5.J8 v2(85.09,26.45)
  TOP w0.254: R23.1 v1(99.45,43.37)
  BOTTOM w0.076: v2(85.09,26.45) 85.24,26.3 85.64,26.3 85.7,26.23 86.71,26.23 86.71,26.23
  BOTTOM w0.254: 86.71,26.23 90.74,26.23 95,30.49 95,33.6 96.42,35.02 96.42,41.2 98.59,43.37 v1(99.45,43.37)
DX SEL PULL DOWN: length 3.1
  TOP w0.254: R31.1 65.79,11.47 65.8,11.48 67.07,11.48 67.1,11.45 JMP13.3
DX SEL PULL UP: length 2.7
  TOP w0.254: R29.2 67.09,16.52 67.1,16.53 JMP13.1
DX_SEL: length 28.4
  TOP w0.076: U5.A1 v2(81.09,30.44)
  BOTTOM w0.254: JMP13.2 66.6,15.51 66.6,24.4 72.63,30.44 v2(81.09,30.44)
HIGH VDD: length 26.6
  BOTTOM w0.508: U4.4 83,51.05 83.59,50.46 83.59,49.2 83.16,48.78 76.91,48.78 76.45,48.33 76.45,46.09 76.03,45.66 76.03,44.83 R56.1 77.42,44.71 77.47,44.65 JMP10.2 JMP10.4 82.88,44.65 83,44.77 R51.2 R52.2 87.32,44.68 R54.2
LOW VDD: length 2.5
  BOTTOM w0.254: R55.2 79.65,42.09 79.63,42.11 JMP10.3
NOM VDD: length 2.3
  BOTTOM w0.254: JMP10.1 79.63,47.19 79.63,47.19 R53.2
OE PULL DOWN: length 2.6
  TOP w0.254: R24.1 67.37,32.16 67.42,32.11 JMP11.3
OE PULL UP: length 3.6
  TOP w0.254: R22.2 69.92,38.67 JMP11.1
OUTPUT ENABLE: length 21.4
  TOP w0.076: U5.B7 v2(84.07,29.35)
  BOTTOM w0.254: JMP11.2 69.56,35.77 81.4,35.77 83.7,33.47 83.7,29.72 v2(84.07,29.35)
SOURCE_CLK_N: length 78.6
  TOP w0.076: 79.34,27.28 80.91,27.28 U5.F1
  TOP w0.254: 79.34,27.28 79.34,27.27 77.12,27.27 74.5,24.65 58.12,24.65 54.52,28.25 53.43,28.25 53.42,28.23 53.04,28.23 53.02,28.25 R118.2 R126.2 51.51,28.25 51.49,28.23 51.11,28.23 51.1,28.25 50.01,28.25 47.02,25.26 42.96,25.26 42.33,25.89 41.41,25.89 40.78,25.26 39.92,25.26 39.25,25.92 38.39,25.92 37.73,25.26 36.87,25.26 36.21,25.92 35.34,25.92 34.68,25.26 33.82,25.26 33.16,25.92 32.3,25.92 31.63,25.26 30.77,25.26 30.11,25.92 29.25,25.92 28.59,25.26 15.82,25.26 13.89,27.19 v1(11.84,27.19)
  BOTTOM w0.254: J18.12 v1(11.84,27.19)
SOURCE_CLK_P: length 78.6
  TOP w0.076: U5.F2 81.57,27.96 81.01,27.96 80.69,27.64 79.92,27.64
  TOP w0.254: v1(12.33,28.19) 14.11,28.19 15.29,27.02 16.56,27.02 17.34,26.23 18.08,26.23 18.87,27.02 19.61,27.02 20.39,26.23 21.13,26.23 21.92,27.02 22.66,27.02 23.44,26.23 24.18,26.23 24.96,27.02 25.7,27.02 26.49,26.23 27.22,26.23 28.01,27.02 47.39,27.02 49.66,29.29 R125.2 R117.2 54.49,29.29 58.34,25.43 74.11,25.43 76.61,27.93 78.31,27.93 78.6,27.64 79.92,27.64
  BOTTOM w0.254: J18.10 v1(12.33,28.19)
SOURCE_DDC_CLK: length 33.7
  TOP w0.076: U5.J3 82.6,26.46 v2(82.59,26.45)
  TOP w0.254: v1(72.51,22.03) 58.51,22.03 56.13,24.41 v1(54.18,24.41) 53.99,24.41 R4.2
  BOTTOM w0.076: v2(82.59,26.45) 79.94,26.45
  BOTTOM w0.254: 79.94,26.45 79.18,27.21 77.69,27.21 v1(72.51,22.03) ; v1(54.18,24.41) 54.18,25.46 R7.2
SOURCE_DDC_SDA: length 38.4
  TOP w0.076: U5.J7 v2(84.21,25.9)
  TOP w0.254: v1(71.93,20.52) 57.6,20.54 54.86,23.28 v1(54.14,23.28) 54.1,23.24 R6.2
  BOTTOM w0.076: 81.77,26.86 82.16,26.86 82.25,26.76 82.71,26.76 82.8,26.67 83.43,26.67 v2(84.21,25.9)
  BOTTOM w0.254: R8.2 54.14,22.51 v1(54.14,23.28) ; 81.77,26.86 81.69,26.86 81.52,27.02 80.25,27.02 79.54,27.73 79.54,27.74 79.53,27.75 76.19,27.75 71.93,23.49 v1(71.93,20.52)
SOURCE_DP_AUX_N_C: length 30
  TOP w0.076: U5.H1 80.75,26.7 80.38,26.33 80.38,25.27
  TOP w0.254: 80.38,25.27 80.38,25.13 79.99,24.74 77.65,24.74 74.28,21.37 58.11,21.37 55.65,23.84 R73.2
SOURCE_DP_AUX_P_C: length 29.6
  TOP w0.076: U5.H2 81.57,26.96 80.18,26.96 79.9,26.67
  TOP w0.254: 79.9,26.67 79.45,26.22 79.45,25.8 78.97,25.32 76.63,25.32 74.07,22.76 58.89,22.76 56.65,25.01 R72.2
SOURCE_HPD_C: length 76.8
  TOP w0.076: v2(81.09,25.95) 81.09,25.96 U5.J1
  TOP w0.254: v1(11.79,23.69) 12.7,23.69 16.63,19.76 v1(72.77,19.76)
  BOTTOM w0.254: v2(81.09,25.95) 80.26,25.11 76.5,25.11 73.52,22.13 R2.2 73.52,19.84 73.44,19.76 v1(72.77,19.76) ; J18.19 v1(11.79,23.69)
SOURCE_TMDS_CLK_P: length 45.7
  TOP w0.254: R72.1 R4.1 R131.1 R129.1 49.92,25.01 48.61,23.7 15.78,23.7 13.78,25.69 v1(11.8,25.69)
  BOTTOM w0.254: J18.15 v1(11.8,25.69)
SOURCE_TMDS_ML_0N: length 78.6
  TOP w0.076: 79.54,28.09 80.72,28.09 80.82,28.2 U5.E1
  TOP w0.254: v1(53.4,35.69) R112.2 R120.2 22.32,35.69 21.84,35.21 20.8,35.21 20.32,35.69 19.27,35.69 18.79,35.21 17.75,35.21 17.27,35.69 16.46,35.69 12.46,31.69 v1(11.98,31.69) ; v1(64.53,26.28) 73.58,26.28 75.87,28.57 78.48,28.57 78.96,28.09 79.54,28.09
  BOTTOM w0.254: J18.3 v1(11.98,31.69) ; v1(64.53,26.28) 63.26,26.28 53.85,35.69 v1(53.4,35.69)
SOURCE_TMDS_ML_0P: length 78.6
  TOP w0.076: 79.82,28.55 80.46,28.55 80.56,28.46 81.57,28.46 U5.E2
  TOP w0.254: v1(11.91,32.69) 16.08,36.86 R119.2 R111.2 v1(53.31,36.86) ; v1(65.08,27.11) 73.03,27.11 75.1,29.18 78.7,29.18 79.33,28.55 79.82,28.55
  BOTTOM w0.254: v1(65.08,27.11) 63.51,27.11 53.76,36.86 v1(53.31,36.86) ; J18.1 v1(11.91,32.69)
SOURCE_TMDS_ML_1N: length 78.6
  TOP w0.076: 79.36,29.16 79.51,29.01 80.47,29.01 80.78,28.7 U5.D1
  TOP w0.254: 79.36,29.16 78.78,29.75 74.2,29.75 72.4,27.95 58.49,27.95 53.26,33.17 R114.2 R122.2 47.73,33.17 46.65,32.1 40.74,32.1 40.03,32.81 39.21,32.81 38.5,32.1 37.69,32.1 36.98,32.81 36.16,32.81 35.45,32.1 34.64,32.1 33.93,32.81 33.12,32.81 32.41,32.1 31.59,32.1 30.88,32.81 30.07,32.81 29.36,32.1 28.54,32.1 27.83,32.81 27.02,32.81 26.31,32.1 15.96,32.1 14.04,30.19 v1(11.97,30.19)
  BOTTOM w0.254: J18.6 v1(11.97,30.19)
SOURCE_TMDS_ML_1P: length 78.6
  TOP w0.076: 80.05,29.62 80.22,29.62 80.87,28.96 81.57,28.96 U5.D2
  TOP w0.254: v1(12.48,31.19) 13.49,31.19 16.33,34.03 16.92,34.03 17.64,33.3 18.44,33.3 19.17,34.03 19.97,34.03 20.69,33.3 21.49,33.3 22.21,34.03 23.01,34.03 23.71,33.33 24.57,33.33 25.26,34.03 45.7,34.03 46.12,34.44 R121.2 R113.2 53.28,34.44 58.98,28.75 71.94,28.75 73.79,30.6 76.23,30.6 76.46,30.37 78.79,30.37 79.54,29.62 80.05,29.62
  BOTTOM w0.254: J18.4 v1(12.48,31.19)
SOURCE_TMDS_ML_2N: length 78.6
  TOP w0.076: 79.47,30.43 79.88,30.02 80.35,30.02 80.68,29.7 U5.B1
  TOP w0.254: v1(58.97,29.58) 71.33,29.58 73.24,31.49 76.44,31.49 76.98,30.96 78.94,30.96 79.47,30.43 ; v1(11.93,28.69) 21.57,28.69 22.28,27.98 23.09,27.98 23.8,28.69 24.62,28.69 25.33,27.98 26.14,27.98 26.85,28.69 27.67,28.69 28.37,27.98 29.19,27.98 29.9,28.69 30.71,28.69 31.42,27.98 32.24,27.98 32.95,28.69 33.76,28.69 34.47,27.98 35.29,27.98 35.99,28.69 36.81,28.69 37.52,27.98 38.33,27.98 39.04,28.69 39.86,28.69 40.57,27.98 41.38,27.98 42.09,28.69 42.91,28.69 43.61,27.98 44.43,27.98 45.14,28.69 47.31,28.69 49.33,30.71 R124.2 R116.2 v1(53.46,30.71)
  BOTTOM w0.254: v1(58.97,29.58) 55.75,29.58 54.62,30.71 v1(53.46,30.71) ; J18.9 v1(11.93,28.69)
SOURCE_TMDS_ML_2P: length 78.6
  TOP w0.076: 80.08,30.68 80.81,29.96 81.57,29.96 U5.B2
  TOP w0.254: v1(53.48,31.83) R115.2 R123.2 48.43,31.83 46.29,29.69 29.99,29.69 29.11,30.57 28.5,30.57 27.62,29.69 26.94,29.69 26.09,30.54 25.42,30.54 24.57,29.69 23.9,29.69 23.05,30.54 22.37,30.54 21.52,29.69 20.85,29.69 20,30.54 19.32,30.54 18.47,29.69 17.8,29.69 16.95,30.54 16.28,30.54 15.43,29.69 v1(12.4,29.69) ; 80.08,30.68 79.13,31.63 77.34,31.63 76.49,32.48 72.84,32.48 70.77,30.41 v1(58.18,30.41)
  BOTTOM w0.254: v1(58.18,30.41) 55.92,30.41 54.5,31.83 v1(53.48,31.83) ; J18.7 v1(12.4,29.69)
SOURCE_TMDS_SDA_N: length 47.5
  TOP w0.254: R73.1 R6.1 R127.1 R128.1 50.22,23.84 47.1,20.72 17.55,20.72 13.08,25.19 v1(12.38,25.19)
  BOTTOM w0.254: J18.16 v1(12.38,25.19)
N16816313: length 2.4
  TOP w0.254: v1(64.84,40.29) 64.84,39.29 D3.2
  BOTTOM w0.254: R50.2 v1(64.84,40.29)
N16845167: length 41.5
  BOTTOM w0.254: 12.3,24.19 J18.18
  BOTTOM w0.508: 12.3,24.19 15.3,24.19 18.88,20.6 R5.2
N17461751: length 12.7
  TOP w0.254: R49.2 v1(101.45,52.7) ; v1(109.66,47.59) J21.7
  BOTTOM w0.254: v1(109.66,47.59) 104.25,53 102.73,53 102.43,52.7 v1(101.45,52.7)
N17461760: length 12.7
  TOP w0.254: J21.9 108.15,46.58 v1(109.76,46.58) ; R57.2 101.44,51.71 v1(101.45,51.72)
  BOTTOM w0.254: v1(101.45,51.72) 101.91,51.72 101.96,51.76 104.58,51.76 v1(109.76,46.58)
N17461769: length 12.7
  TOP w0.254: R58.2 v1(101.01,50.52) ; v1(106.53,49.1) 108.14,49.1 J21.4
  BOTTOM w0.254: v1(106.53,49.1) 105.06,49.1 104.72,48.76 104.72,46.81 104.42,46.51 103.37,46.51 102.48,47.4 102.48,49.51 101.47,50.52 v1(101.01,50.52)
N17461772: length 12.7
  TOP w0.254: R59.2 v1(101.01,49.52) ; J21.6 108.13,48.11 v1(106.48,48.11)
  BOTTOM w0.254: v1(101.01,49.52) 101.72,48.81 101.72,47.02 103.54,45.2 104.67,45.2 105.45,45.97 105.45,47.8 105.75,48.11 v1(106.48,48.11)
N17461775: length 12.6
  TOP w0.254: R60.2 101.12,48.44 102.34,49.65 102.34,52.15 103.04,52.85 105.75,52.85 106.38,52.22 106.38,50.92 106.71,50.59 J21.1
N17461784: length 12.7
  TOP w0.254: R61.2 101.5,47.44 103.04,48.98 103.04,51.47 103.56,51.99 104.96,51.99 105.53,51.42 105.53,50.31 106.26,49.59 J21.3
N17461793: length 12.7
  TOP w0.254: R62.2 101.18,46.23 101.19,46.23 101.66,46.23 103.67,48.24 103.67,49.48 104.17,49.97 104.96,49.97 105.9,49.03 105.9,46.63 106.44,46.09 J21.10
N17461802: length 12.7
  TOP w0.254: J21.12 106.42,45.09 106.01,44.67 105.53,44.67 105.19,45.01 105.19,47.37 104.76,47.81 104.17,47.81 103.15,46.78 103.15,45.06 102.87,44.78 102.36,44.78 101.92,45.22 R63.2
N17518625: length 7.5
  TOP w0.254: J21.18 105.07,42.09 103.3,40.32 R20.1
N17521117: length 12.7
  TOP w0.254: v1(109.69,12.03) J22.7 ; R64.2 v1(101.34,16.98)
  BOTTOM w0.254: v1(101.34,16.98) 101.99,16.98 102.21,17.2 103.76,17.2 103.99,16.98 104.74,16.98 v1(109.69,12.03)
N17521123: length 12.7
  TOP w0.254: v1(101.34,16.11) 101.26,16.11 101.24,16.09 R65.2 ; J22.9 109.04,11.03 v1(109.69,11.03)
  BOTTOM w0.254: v1(109.69,11.03) 104.61,16.11 104.1,16.11 103.88,15.89 102.49,15.89 102.27,16.11 v1(101.34,16.11)
N17521129: length 12.7
  TOP w0.254: R66.2 v1(101.01,15.07) ; J22.4 108.14,13.52 v1(106.34,13.52)
  BOTTOM w0.254: v1(106.34,13.52) 105.47,13.52 104.91,12.96 104.91,11.56 104.38,11.02 103.4,11.02 102.86,11.56 102.86,14.31 102.1,15.07 v1(101.01,15.07)
N17521131: length 12.7
  TOP w0.254: R67.2 v1(101.04,13.96) ; v1(106.59,12.53) 108.13,12.54 J22.6
  BOTTOM w0.254: v1(101.04,13.96) 101.58,13.96 102.14,13.4 102.14,10.76 102.89,10.01 105.01,10.01 105.69,10.69 105.69,12.22 106,12.53 v1(106.59,12.53)
N17521133: length 12.7
  TOP w0.254: J22.1 106.64,15.03 105.98,15.68 105.98,16.71 105.35,17.35 102.88,17.35 102,16.46 102,13.77 100.99,12.76 R68.2
N17521137: length 12.7
  TOP w0.254: R69.2 101.08,11.85 102.61,13.38 102.61,15.77 103.54,16.69 104.78,16.69 105.2,16.27 105.2,15.42 106.59,14.03 J22.3
N17521143: length 12.7
  TOP w0.254: J22.10 106.42,10.53 105.68,11.26 105.68,13.83 104.93,14.58 103.97,14.58 103.32,13.93 103.32,13.1 101.23,11.01 R70.2
N17521149: length 12.7
  TOP w0.254: J22.12 105.35,9.53 105.01,9.87 105.01,12.61 104.56,13.06 104.19,13.06 103.6,12.47 103.6,11.07 102.63,10.1 R71.2
N17522573: length 6.9
  TOP w0.254: R43.2 102.83,6.55 103.02,6.74 105.99,6.74 106.28,7.03 J22.17
N17522869: length 13.4
  TOP w0.254: R44.1 101.86,3.31 101.88,3.29 102.47,3.29 104.5,5.33 110.2,5.33 110.44,5.56 110.44,6.31 110.22,6.53 J22.18
N17527182: length 31.3
  TOP w0.076: U5.A3 v2(82.09,29.96)
  BOTTOM w0.076: TP1.1 70.92,9.76 70.09,10.59 70.09,25.29 74.75,29.96 v2(82.09,29.96)
N17527888: length 11.7
  TOP w0.076: U5.A7 v2(84.09,29.96)
  BOTTOM w0.254: TP2.1 81.93,36.96 84.36,34.52 84.36,30.23 v2(84.09,29.96)
N17528001: length 30.1
  TOP w0.076: U5.C1 v2(81.06,29.35)
  BOTTOM w0.076: v2(81.06,29.35) 74.57,29.35 70.34,25.13 70.34,11.66 72.2,9.8 TP3.1
N17528028: length 10.4
  TOP w0.076: U5.G9 v2(85.59,27.2)
  BOTTOM w0.076: v2(85.59,27.2) 85.94,27.2 86.95,28.21 88.07,28.21 92.5,32.64 TP4.1
N17528033: length 30.9
  TOP w0.076: U5.G1 v2(81.57,27.44)
  BOTTOM w0.076: v2(81.57,27.44) 81.57,27.52 80.96,28.13 75.3,28.13 71.5,24.33 71.5,16.68 78.39,9.79 TP5.1
N17528049: length 13.5
  TOP w0.076: U5.F6 v2(83.83,27.4)
  BOTTOM w0.076: v2(83.83,27.4) 84.22,27.4 84.37,27.56 85.9,27.56 86.82,28.48 87.91,28.48 91.44,32.01 91.44,34.44 TP6.1
N17528125: length 32.7
  TOP w0.076: U5.F5 v2(83.33,27.39)
  BOTTOM w0.076: v2(83.33,27.39) 82.36,27.39 81.39,28.35 75.13,28.35 71.29,24.51 71.29,15.66 77.17,9.79 TP8.1
N17528132: length 17
  TOP w0.076: v2(83.6,28.46) U5.D6
  BOTTOM w0.076: v2(83.6,28.46) 85.83,28.46 86.5,29.13 87.54,29.13 90.64,32.23 90.64,37.58 TP7.1
N17528155: length 14
  TOP w0.076: U5.C9 85.08,29.45 v2(85.08,29.45)
  BOTTOM w0.254: TP10.1 82.44,38.28 85.08,35.64 v2(85.08,29.45)
N17528163: length 31.8
  TOP w0.076: U5.F4 v2(82.54,27.7)
  BOTTOM w0.076: v2(82.54,27.7) 82.17,28.07 81.99,28.07 81.48,28.58 74.98,28.58 71.08,24.68 71.08,14.65 75.94,9.79 TP9.1
N17528201: length 32.3
  TOP w0.076: v2(83.1,28.49) 83.3,28.7 U5.D5
  BOTTOM w0.076: v2(83.1,28.49) 82.89,28.7 82.03,28.7 81.7,29.03 74.64,29.03 70.58,24.98 70.58,12.66 73.45,9.79 TP12.1
N17528206: length 15.4
  TOP w0.076: U5.E6 v2(84.15,28.12)
  BOTTOM w0.076: v2(84.15,28.12) 85.8,28.12 86.61,28.93 87.64,28.93 90.92,32.21 90.92,36.52 TP11.1
N17528242: length 31.7
  TOP w0.076: U5.E4 v2(82.54,28.2)
  BOTTOM w0.076: TP13.1 74.7,9.8 70.82,13.68 70.82,24.84 74.78,28.8 81.62,28.8 81.96,28.46 82.28,28.46 v2(82.54,28.2)
N17528247: length 15
  TOP w0.076: v2(83.58,27.95) 83.57,27.97 U5.E5
  BOTTOM w0.076: v2(83.58,27.95) 83.88,27.95 84.03,27.8 85.81,27.8 86.73,28.71 87.78,28.71 91.16,32.1 91.16,35.47 TP14.1
N17577047: length 2.7
  TOP w0.254: D5.2 v1(63.05,40.42)
  BOTTOM w0.254: R132.2 63.05,39.49 63.05,39.49 v1(63.05,40.42)
N17584630: length 7.2
  TOP w0.254: J21.17 103.04,42.59 101.92,41.47 R25.2
N17593880: length 37
  TOP w1.016: J18.23 3.47,35.35 C75.1 3.52,33.44 R134.1
  BOTTOM w0.254: 3.57,26.19 3.57,26.19 J18.14
  BOTTOM w1.016: J18.21 J18.23 J18.22 J18.20

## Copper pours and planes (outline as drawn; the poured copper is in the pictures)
9V_WALL_IN on BOTTOM (solid shape): 73.49,47.84 73.49,42.06 71.48,40.05 66.98,40.05 66,41.03 66,43.75 67.41,45.15 70.45,45.15 72.03,46.74 72.03,48.07 72.05,48.04 72.28,48.04 72.31,48.07 73.26,48.07
GND on L2: 1.02,37.54 56.45,37.54 62.44,43.52 62.44,55.54 117.48,55.54 117.48,1.02 62.45,1.02 62.45,13.08 56.22,19.31 1.02,19.31
GND on L5: 1.52,19.82 1.52,37.03 56.66,37.03 62.95,43.31 62.95,55.04 116.97,55.04 116.97,1.52 62.96,1.52 62.96,13.29 56.43,19.82
3P3V on BOTTOM (solid shape): 91.01,54.78 91.01,50.27 90.78,50.04 88.49,50.04 88.16,50.36 88.16,54.77 88.31,54.91 90.88,54.91
3P3V on BOTTOM: 73.65,32.93 73.65,35.08 71.07,35.08 71.07,32.93
3P3V on L3: 1.52,19.82 1.52,37.03 56.66,37.03 62.95,43.31 62.95,55.04 116.97,55.04 116.97,1.52 62.96,1.52 62.96,13.29 56.43,19.82
3P3V_R on BOTTOM: 82.94,26.01 82.25,26.01 81.52,25.28 81.52,24.46 83.92,24.46 83.92,25.45 83.76,25.6 83.26,25.6 82.96,25.9 82.96,25.99
3P3V_R on BOTTOM: 81.72,30.42 82.16,30.42 82.4,30.66 83.14,30.66 83.32,30.85 83.32,31.47 79.82,31.47 79.68,31.33 79.68,30.94 79.75,30.88 81.28,30.88 81.72,30.43
3P3V_R on BOTTOM: 74.25,32.95 74.25,35.09 76.09,35.09 76.09,32.95
3P3V_R on L3: 74.25,35.04 74.25,31.71 75.36,30.6 81.44,30.6 82.02,30.02 82.02,24.93 84.32,24.93 84.64,25.25 84.64,31.49 83.92,32.21 76.88,32.21 76.09,33 76.09,35.04
3P3V_REG on BOTTOM (solid shape): 86.65,54.07 86.65,51.55 86.66,51.54 86.66,48.21 86.82,48.05 88.51,48.05 90.05,46.52 90.05,42.59 88.87,41.41 82.54,41.41 82.36,41.59 82.36,42.54 82.66,42.84 88.17,42.84 88.64,43.32 88.64,45.59 88.26,45.97 82.8,45.97 82.19,46.58 82.19,47.8 82.43,48.03 83.84,48.03 84.52,48.71 84.52,51.05 84.51,51.06 84.51,53 84.27,53.24 80.39,53.24 80.27,53.35 80.27,53.83 80.39,53.94 80.39,53.95 82.95,53.95 83.32,54.33 86.39,54.33
5V/3P3V on L4: 1.52,19.82 1.52,37.03 56.66,37.03 62.95,43.31 62.95,55.04 116.97,55.04 116.97,1.52 62.96,1.52 62.96,13.29 56.43,19.82
Net_9 on TOP (solid shape): 84.08,11.8 84.15,11.62 84.27,11.5 84.48,11.39 84.69,11.35 84.55,10.64 83.97,10.64 83.8,10.09 84.41,10.09 84.27,9.23 84.38,8.74 84.52,8.5 84.76,8.35 84.91,8.33 85.13,8.34 85.16,8.35 85.34,8.41 85.49,9.2 85.4,9.13 85.28,9.12 85.18,9.14 85.14,9.31 85.28,10.06 85.78,10.06 85.95,10.64 85.45,10.64 85.58,11.23 85.82,11.32 86.02,11.35 86.23,11.36 86.64,11.28 86.87,11.19 86.92,11.11 86.89,10.89 86.96,10.37 87,10.25 87.09,10.1 87.16,9.74 87.17,9.41 87.1,8.7 86.99,8.44 86.02,8.02 85.27,7.37 85.02,6.81 85.14,6.16 85.35,5.74 84.99,5.79 84.73,5.87 84.47,5.97 84.08,6.16 83.57,6.53 83.12,7.18 82.78,7.97 82.58,8.49 82.4,8.68 82.18,8.77 81.92,8.77 81.74,8.72 81.67,8.68 81.59,8.56 81.47,8.45 81.36,8.47 81.16,8.55 81.02,8.68 80.82,8.99 80.63,9.4 80.32,9.83 79.97,10.28 80.39,10.28 82.04,10.28 82.04,13.04 84.08,13.04
Net_10 on TOP (solid shape): 85.4,11.2 84.99,9.38 84.92,9.07 84.49,9.07 84.44,9.14 84.42,9.23 84.84,11.25 84.84,11.26

Small or netless copper shapes (teardrops, artwork), in the pictures only: 1 on TOP

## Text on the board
Ref Des/Silkscreen Bottom: NOM VDD | LOW VDD | HIGH VDD
Ref Des/Silkscreen Top: 3P3V | GND | Dx_SEL_PD | Dx_SEL_PU | Dx_SEL | OE_PD | OE_PU | OE | A7 | C9 | D6 | E5 | F6 | G9 | E6 | AUX_SEL_PU | AUX_SEL | AUX_SEL_PD | A3 | C1 | D5 | E4 | F4 | F5 | G1 | PORT C | HD3SS215EVM | 6573507 | 9V | REVC | PORT B | PORT A
PAGE_OUTLINE: GENERAL NOTES. UNLESS OTHERWISE SPECIFIED | 1.  ALL FABRICATION ITEMS MUST MEET OR EXCEED BEST | INDUSTRY PRACTICE : IPC-A-600C (Commercial std.) | 2.  LAMINATE MATERIAL  :  FR4 POLYCLAD 370 or EQUIVALENT | 3.  COPPER WEIGHT  : 1oz START INTERNAL, 1/2oz START EXTERNAL | 4.  FINISHED BOARD THICKNESS :  .063  +/- 10% | 5.  MAXIMUM WARP AND TWIST TO BE :  .005 INCH PER INCH | 6.  MINIMUM COPPER WALL THICKNESS OF PLATED-THRU | HOLES TO BE .001 INCH. THERE MUST BE 1MIL OR GREATER PLATING ON | EACH SIDE OF THE BARREL WHEN VIEWED IN THE CROSS SECTION | 7.  MINIMUM ANNULAR RING OF PLATED-THRU HOLES | TO BE .002 INCH | 8.  MAXIMUM ALLOWABLE LINE REDUCTION TO BE | 20% OR .002 WHICHEVER IS SMALLER | 10. 0.010 SIGNAL LINES ON LAYER 1 & 6 TO BE | IMPEDANCE CONTROLLED 50 OHMS +/- 10% | 11. DIELECTRIC CONSTANTS ARE         CORE : 4.1 | PREPREG : 4.1 | 13. A CROSS SECTION MOUNT AND DIGITAL PHOTO'S OF VIA'S TO BE PROVIDED | 14. USE THE (DRPP) DUTCH REVERSE PLATING PROCESS | PROCESS NOTES | 1. CIRCUITRY ON OUTER LAYERS TO BE PLATED WITH : NICKEL GOLD | 2. SOLDERMASK BOTH SIDES PER ARTWORK  :  GREEN LPI | 3. SILKSCREEN BOTH SIDES PER ARTWORK  :  COLOR = WHITE
DIMENSION: 25mil | 6.5mil | 8mil | 1 | 2 | 3 | 4 | TOP | L2 | L3 | L4 | L5 | BOTTOM
NCLEGEND-1-6: FIGURE | SIZE | 140.0 | 120.0 | 38.0 | 12.0 | 8.0 | 5.0 | 63.4 | 33.5 | 106.3x35.4 | 82.7x35.4 | DRILL CHART: TOP to BOTTOM | ALL UNITS ARE IN MILS | TOLERANCE | +0.0/-0.0 | +2.0/-2.0 | +3.0/-12.0 | PLATED | NON-PLATED | QTY | 1 | 2 | 16 | 14 | 146 | 51 | 4 | 6
